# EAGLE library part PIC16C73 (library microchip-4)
MICROCONTROLLER EPROM/ROM-based
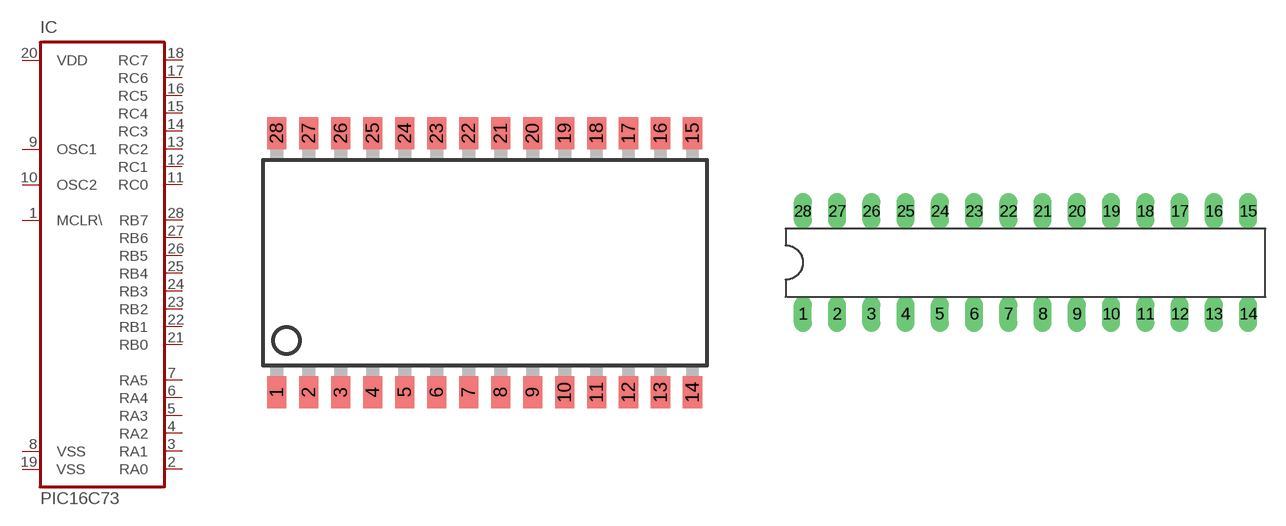
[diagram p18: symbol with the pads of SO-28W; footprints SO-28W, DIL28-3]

Designator prefix IC

## PIC16C73SO  [SO-28W]
1  MCLR\  in
2  RA0
3  RA1
4  RA2
5  RA3
6  RA4
7  RA5
8  VSS  pwr
9  OSC1
10  OSC2
11  RC0
12  RC1
13  RC2
14  RC3
15  RC4
16  RC5
17  RC6
18  RC7
19  VSS  pwr
20  VDD  pwr
21  RB0
22  RB1
23  RB2
24  RB3
25  RB4
26  RB5
27  RB6
28  RB7

## PIC16C73P  [DIL28-3]
Pads as for SO-28W

## Footprint SO-28W (pad centres in mm)
Small Outline Wide Plastic Gull Wing 300-mil body, package type SO
smd 0.762 x 1.27: 1 -7.62,-5.207; 2 -6.35,-5.207; 3 -5.08,-5.207; 4 -3.81,-5.207; 5 -2.54,-5.207; 6 -1.27,-5.207; 7 0,-5.207; 8 1.27,-5.207; 9 2.54,-5.207; 10 3.81,-5.207; 11 5.08,-5.207; 12 6.35,-5.207; 13 7.62,-5.207; 14 8.89,-5.207; 15 8.89,5.08; 16 7.62,5.08; 17 6.35,5.08; 18 5.08,5.08; 19 3.81,5.08; 20 2.54,5.08; 21 1.27,5.08; 22 0,5.08; 23 -1.27,5.08; 24 -2.54,5.08; 25 -3.81,5.08; 26 -5.08,5.08; 27 -6.35,5.08; 28 -7.62,5.08

## Footprint DIL28-3 (pad centres in mm)
Dual In Line package type P
drill 0.813 long: 1 -16.51,-3.81; 2 -13.97,-3.81; 3 -11.43,-3.81; 4 -8.89,-3.81; 5 -6.35,-3.81; 6 -3.81,-3.81; 7 -1.27,-3.81; 8 1.27,-3.81; 9 3.81,-3.81; 10 6.35,-3.81; 11 8.89,-3.81; 12 11.43,-3.81; 13 13.97,-3.81; 14 16.51,-3.81; 15 16.51,3.81; 16 13.97,3.81; 17 11.43,3.81; 18 8.89,3.81; 19 6.35,3.81; 20 3.81,3.81; 21 1.27,3.81; 22 -1.27,3.81; 23 -3.81,3.81; 24 -6.35,3.81; 25 -8.89,3.81; 26 -11.43,3.81; 27 -13.97,3.81; 28 -16.51,3.81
